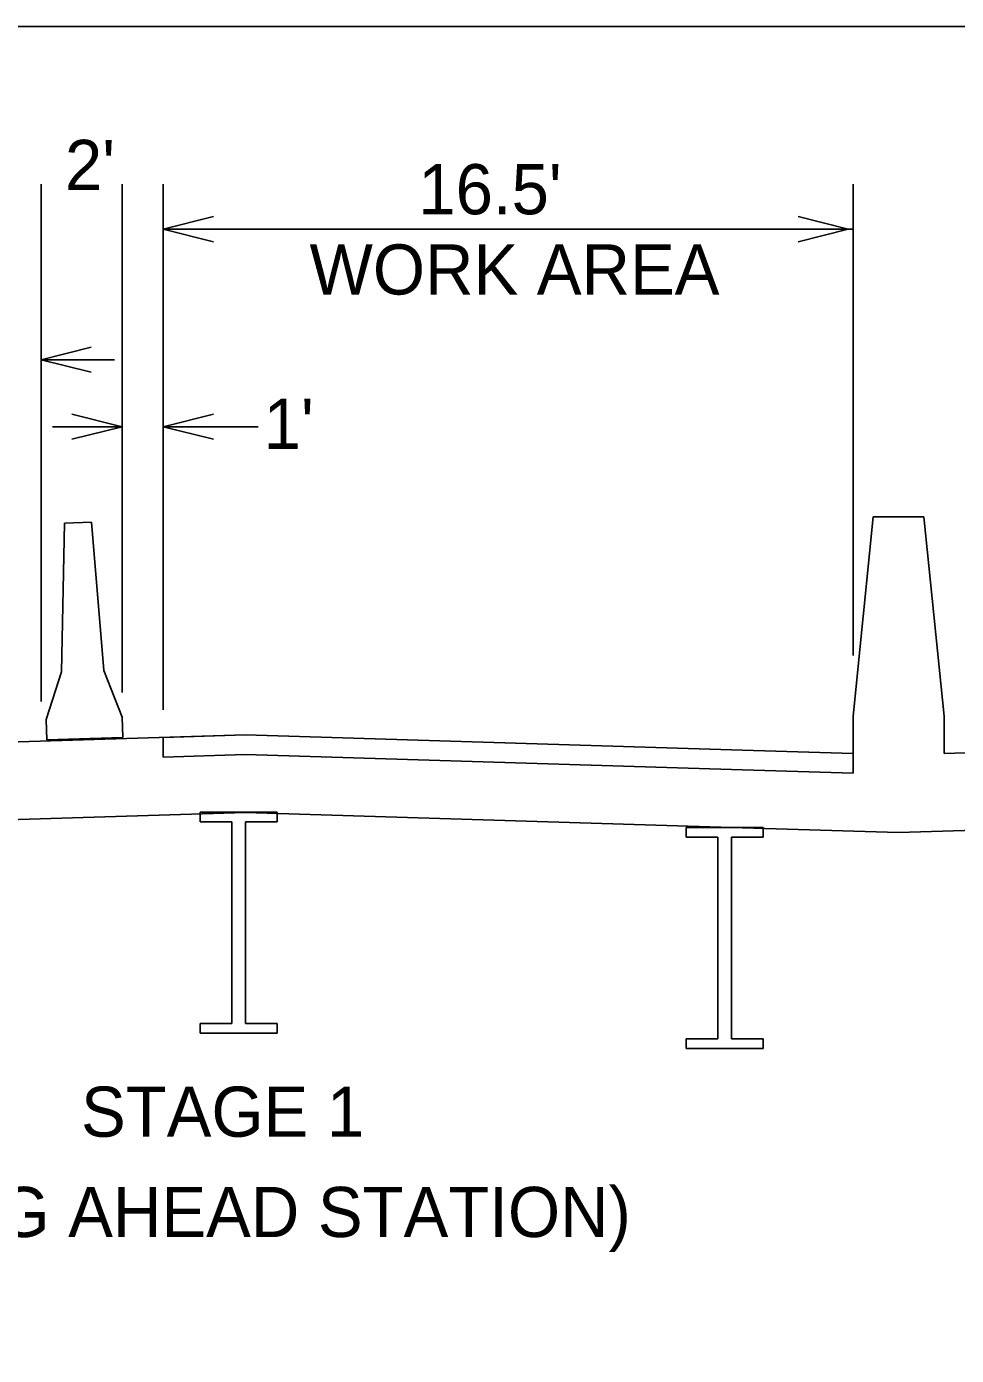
# Model space of a CAD drawing. Extents: x 10133 to 81668, y 7924 to 11018.
# Drawn here: x 11481 to 12170, y 8960 to 9944 of the extents above; entities that cross this region are included whole.
import ezdxf

# ---------------------------------------------------------------- set-up
doc = ezdxf.new("R2010")
doc.units = 0
for name, color, linetype in [('dsnCellElements', 7, 'Continuous'), ('SheetAddendum', 7, 'Continuous'), ('SheetBorder', 7, 'Continuous'), ('ShtPlotIdentification', 7, 'Continuous')]:
    doc.layers.add(name, color=color, linetype=linetype)

msp = doc.modelspace()

# ---------------------------------------------------------------- linework, layer by layer
at = {"layer": 'dsnCellElements'}
for p, q in [((12108.02, 9580.86), (12093.02, 9433.01)), ((12145.52, 9580.86), (12108.02, 9580.86)), ((12145.52, 9580.86), (12160.52, 9433.01)), ((11506.8, 9465.98), (11509, 9576.1)), ((11528.99, 9576.73), (11509, 9576.1)), ((11538.04, 9466.95), (11528.99, 9576.73)), ((11495.4, 9430.61), (11506.8, 9465.98)), ((11551.62, 9432.36), (11538.04, 9466.95)), ((11552.09, 9417.37), (11551.62, 9432.36)), ((12093.02, 9405.49), (12093.02, 9433.01)), ((12160.52, 9405.49), (12160.52, 9433.01)), ((11495.86, 9415.62), (11495.4, 9430.61)), ((11283.02, 9408.06), (11643.02, 9419.26)), ((11495.86, 9415.62), (11552.09, 9417.37)), ((11582.09, 9417.37), (11582.09, 9402.79)), ((12003.02, 9408.06), (11643.02, 9419.26)), ((11582.09, 9402.79), (11643.02, 9404.69)), ((12003.02, 9393.49), (11643.02, 9404.69)), ((12093.02, 9405.49), (12003.02, 9408.06)), ((12093.02, 9405.49), (12093.02, 9390.91)), ((12160.52, 9405.49), (12278.68, 9408.87)), ((12093.02, 9390.91), (12003.02, 9393.49)), ((11283.02, 9350.52), (11643.02, 9361.72)), ((11609.48, 9354.76), (11609.48, 9361.92)), ((11666.53, 9361.92), (11609.48, 9361.92)), ((11632.99, 9354.76), (11609.48, 9354.76)), ((11632.99, 9354.76), (11632.99, 9205.34)), ((12003.02, 9350.52), (11643.02, 9361.72)), ((11666.53, 9354.76), (11643.02, 9354.76)), ((11643.02, 9354.76), (11643.02, 9205.34)), ((11666.53, 9354.76), (11666.53, 9361.92)), ((11969.48, 9343.56), (11969.48, 9350.72)), ((12026.53, 9350.72), (11969.48, 9350.72)), ((11992.99, 9343.56), (11969.48, 9343.56)), ((11992.99, 9343.56), (11992.99, 9194.14)), ((12126.77, 9346.97), (12003.02, 9350.52)), ((12003.02, 9343.56), (12003.02, 9194.14)), ((12026.53, 9343.56), (12003.02, 9343.56)), ((12026.53, 9343.56), (12026.53, 9350.72)), ((12126.77, 9346.97), (12278.68, 9351.33)), ((11632.99, 9205.34), (11609.48, 9205.34)), ((11609.48, 9205.34), (11609.48, 9198.17)), ((11666.53, 9205.34), (11643.02, 9205.34)), ((11666.53, 9205.34), (11666.53, 9198.17)), ((11666.53, 9198.17), (11609.48, 9198.17)), ((11992.99, 9194.14), (11969.48, 9194.14)), ((11969.48, 9194.14), (11969.48, 9186.97)), ((12026.53, 9186.97), (11969.48, 9186.97)), ((12026.53, 9194.14), (12003.02, 9194.14)), ((12026.53, 9194.14), (12026.53, 9186.97))]:
    msp.add_line(p, q, dxfattribs=at)
at = {"layer": 'SheetAddendum'}
for p, q in [((11491.62, 9444.08), (11491.62, 9827.23)), ((11551.62, 9450.68), (11551.62, 9827.23)), ((11582.09, 9437.87), (11582.09, 9827.23)), ((12093.02, 9477.95), (12093.02, 9827.23)), ((12093.02, 9793.9), (11582.09, 9793.9)), ((11491.62, 9697.19), (11546.04, 9697.19)), ((11551.62, 9647.52), (11500.16, 9647.52)), ((11652.45, 9647.52), (11582.09, 9647.52))]:
    msp.add_line(p, q, dxfattribs=at)
for points in [[(11619.24, 9803.19), (11582.09, 9793.9), (11619.24, 9784.62)], [(12052.28, 9803.19), (12089.43, 9793.9), (12052.28, 9784.62)], [(11528.77, 9706.48), (11491.62, 9697.19), (11528.77, 9687.9)], [(11514.47, 9656.81), (11551.62, 9647.52), (11514.47, 9638.23)], [(11619.24, 9656.81), (11582.09, 9647.52), (11619.24, 9638.23)]]:
    msp.add_lwpolyline(points, dxfattribs=at)
at = {"layer": 'SheetBorder'}
msp.add_lwpolyline([(10132.52, 9944.02), (13267.53, 9944.02), (13267.53, 7924.02), (10132.52, 7924.02)], close=True, dxfattribs=at)
at = {"layer": 'ShtPlotIdentification'}
msp.add_lwpolyline([(12093.02, 9390.91), (12003.02, 9393.49), (11643.02, 9404.69), (11582.09, 9402.79), (11582.09, 9417.37), (11643.02, 9419.26), (12003.02, 9408.06), (12093.02, 9405.49)], close=True, dxfattribs=at)

# ---------------------------------------------------------------- texts
at = {"layer": 'SheetAddendum'}
for s, height, p in [("2'", 37.15, (11509.25, 9822.95)), ("16.5'", 37.15, (11771.04, 9804.95)), ('WORK AREA', 37.15, (11690.47, 9745.51)), ("1'", 37.15, (11656.48, 9631.16)), ('STAGE 1', 37.15, (11521.16, 9121.52)), ('(LOOKING AHEAD STATION)', 37.1501, (11254.97, 9047.22))]:
    msp.add_text(s, height=height, dxfattribs=at).set_placement(p)

doc.saveas('drawing.dxf')
